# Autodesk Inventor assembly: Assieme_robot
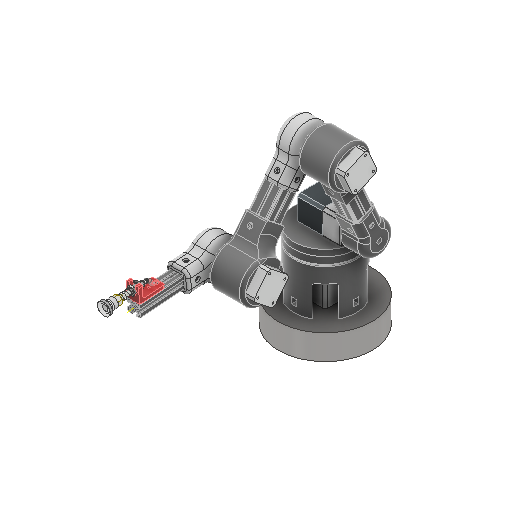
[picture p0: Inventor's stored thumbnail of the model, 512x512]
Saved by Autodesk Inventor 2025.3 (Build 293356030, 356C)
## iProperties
Created: 2026-03
Part Number: Assieme_robot
Document SubType Name: Assembly
Designer: R5800u
Author: R5800u
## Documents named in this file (17)
- C:\Users\R5800u\Desktop\robot_riduttore_cicloidale3\Workgroups\NotInProject\Assieme_robot.iam
- C:\Users\R5800u\Desktop\robot_riduttore_cicloidale3\Workgroups\NotInProject\riduttore_cicloidale_nema17-47mm.iam
- C:\Users\R5800u\Desktop\robot_riduttore_cicloidale3\Workgroups\NotInProject\braccio1.ipt
- C:\Users\R5800u\Desktop\robot_riduttore_cicloidale3\Workgroups\NotInProject\tslot-20x20-100mm.ipt
- C:\Users\R5800u\Desktop\robot_riduttore_cicloidale3\Workgroups\NotInProject\riduttore_cicloidale_nema17-40mm.iam
- C:\Users\R5800u\Desktop\robot_riduttore_cicloidale3\Workgroups\NotInProject\base_ferro.ipt
- C:\Users\R5800u\Desktop\robot_riduttore_cicloidale3\Workgroups\NotInProject\ISO 104 - 1 11 50 x 70 x 14.ipt
- C:\Users\R5800u\Desktop\robot_riduttore_cicloidale3\Workgroups\NotInProject\blocco_base.ipt
- C:\Users\R5800u\Desktop\robot_riduttore_cicloidale3\Workgroups\NotInProject\disco_base1.ipt
- C:\Users\R5800u\Desktop\robot_riduttore_cicloidale3\Workgroups\NotInProject\disco_base2.ipt
- C:\Users\R5800u\Documents\Inventor\Content Center Files\R2025\it-IT\AS 1112 (2)\AS 1112 - M5  Tipo 5.ipt
- C:\Users\R5800u\Documents\Inventor\Content Center Files\R2025\it-IT\ANSI B18.3.1M(6)\ANSI B18.3.1M - M5x0,8 x 50(1).ipt
- C:\Users\R5800u\Desktop\robot_riduttore_cicloidale3\Workgroups\NotInProject\blocco_nema.ipt
- C:\Users\R5800u\Desktop\robot_riduttore_cicloidale3\Workgroups\NotInProject\blocco_albero_nema.ipt
- C:\Users\R5800u\Desktop\robot_riduttore_cicloidale3\Workgroups\NotInProject\ventosa_20mm.iam
- C:\Users\R5800u\Documents\Inventor\Content Center Files\R2025\it-IT\AS 1420\AS 1420 - 1973 - M3 x 16.ipt
- C:\Users\R5800u\Desktop\robot_riduttore_cicloidale3\Workgroups\NotInProject\Assieme_frame_tslot.iam
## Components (28 placed, 16 different names)
1. riduttore_cicloidale_nema17-47mm:1 [sub-assembly] — Allineato:1, Coincidente:7, Angolo:1, Coincidente:20, Coincidente:21, Rotazionale:2, Allineato:13
2. braccio1:1 — Coincidente:7, Angolo:1, Coincidente:10, Coincidente:11, Coincidente:56, Coincidente:59, Rotazionale:2
3. tslot-20x20-100mm:1
4. riduttore_cicloidale_nema17-40mm:1 [sub-assembly] — Coincidente:13, Allineato:3, Angolo:2, Coincidente:16, Coincidente:18
5. base_ferro:1
6. UNI ISO 104 1 11 50 x 70 x 14:1 — Coincidente:14, Coincidente:15
7. blocco_base:1
8. disco_base1:1 — Coincidente:16, Coincidente:17, Coincidente:19, Angolo:6
9. disco_base2:1 — Coincidente:18, Coincidente:19, Angolo:3, Coincidente:20
10. Vite forgiata a testa incassata - Metrico M5x0,8 x 50:1 — Coincidente:30
11. Vite forgiata a testa incassata - Metrico M5x0,8 x 50:2 — Coincidente:32
12. Vite forgiata a testa incassata - Metrico M5x0,8 x 50:3 — Coincidente:34
13. Vite forgiata a testa incassata - Metrico M5x0,8 x 50:4 — Coincidente:36
14. blocco_nema:1
15. riduttore_cicloidale_nema17-40mm:2 [sub-assembly] — Coincidente:39, Angolo:4, Allineato:10, Coincidente:40
16. blocco_albero_nema:1 — Coincidente:40, Coincidente:41, Coincidente:42, Coincidente:43, Coincidente:44
17. tslot-20x20-100mm:2
18. blocco_nema:2
19. riduttore_cicloidale_nema17-40mm:3 [sub-assembly] — Coincidente:47, Angolo:5, Coincidente:48, Coincidente:49
20. blocco_albero_nema:2 — Coincidente:49, Coincidente:50, Coincidente:51, Coincidente:52, Coincidente:53, Coincidente:55
21. ventosa_20mm:1 [sub-assembly] — Coincidente:51, Coincidente:52, Coincidente:53
22. AS 1420 - Metrico M3 x 16:1 — Coincidente:55
23. Assieme_frame_tslot:1 [sub-assembly] — Coincidente:57, Coincidente:58, Coincidente:59, Coincidente:63
24. Assieme_frame_tslot:2 [sub-assembly] — Coincidente:60, Coincidente:61, Coincidente:62
25. AS 1112 (2) - Metrico M5  Tipo 5:1
26. AS 1112 (2) - Metrico M5  Tipo 5:2
27. AS 1112 (2) - Metrico M5  Tipo 5:3
28. AS 1112 (2) - Metrico M5  Tipo 5:4
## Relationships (49: Mate 38, Angle 6, Flush 4, RevoluteJoint 1)
- Allineato:1 [Flush]: riduttore_cicloidale_nema17-47mm:1
- Coincidente:7 [Mate]: riduttore_cicloidale_nema17-47mm:1 ↔ braccio1:1
- Angolo:1 [Angle]: riduttore_cicloidale_nema17-47mm:1 ↔ braccio1:1
- Coincidente:10 [Mate]: braccio1:1
- Coincidente:11 [Mate]: braccio1:1
- Coincidente:13 [Mate]: riduttore_cicloidale_nema17-40mm:1
- Allineato:3 [Flush]: riduttore_cicloidale_nema17-40mm:1
- Coincidente:14 [Mate]: UNI ISO 104 1 11 50 x 70 x 14:1
- Coincidente:15 [Mate]: UNI ISO 104 1 11 50 x 70 x 14:1
- Angolo:2 [Angle]: riduttore_cicloidale_nema17-40mm:1
- Coincidente:16 [Mate]: riduttore_cicloidale_nema17-40mm:1 ↔ disco_base1:1
- Coincidente:17 [Mate]: disco_base1:1
- Coincidente:18 [Mate]: riduttore_cicloidale_nema17-40mm:1 ↔ disco_base2:1
- Coincidente:19 [Mate]: disco_base1:1 ↔ disco_base2:1
- Angolo:3 [Angle]: disco_base2:1
- Coincidente:20 [Mate]: riduttore_cicloidale_nema17-47mm:1 ↔ disco_base2:1
- Coincidente:21 [Mate]: riduttore_cicloidale_nema17-47mm:1
- Coincidente:30 [Mate]: Vite forgiata a testa incassata - Metrico M5x0,8 x 50:1
- Coincidente:32 [Mate]: Vite forgiata a testa incassata - Metrico M5x0,8 x 50:2
- Coincidente:34 [Mate]: Vite forgiata a testa incassata - Metrico M5x0,8 x 50:3
- Coincidente:36 [Mate]: Vite forgiata a testa incassata - Metrico M5x0,8 x 50:4
- Coincidente:39 [Mate]: riduttore_cicloidale_nema17-40mm:2
- Angolo:4 [Angle]: riduttore_cicloidale_nema17-40mm:2
- Allineato:10 [Flush]: riduttore_cicloidale_nema17-40mm:2
- Coincidente:40 [Mate]: riduttore_cicloidale_nema17-40mm:2 ↔ blocco_albero_nema:1
- Coincidente:41 [Mate]: blocco_albero_nema:1
- Coincidente:42 [Mate]: blocco_albero_nema:1
- Coincidente:43 [Mate]: blocco_albero_nema:1
- Coincidente:44 [Mate]: blocco_albero_nema:1
- Coincidente:47 [Mate]: riduttore_cicloidale_nema17-40mm:3
- Angolo:5 [Angle]: riduttore_cicloidale_nema17-40mm:3
- Coincidente:48 [Mate]: riduttore_cicloidale_nema17-40mm:3
- Coincidente:49 [Mate]: riduttore_cicloidale_nema17-40mm:3 ↔ blocco_albero_nema:2
- Coincidente:50 [Mate]: blocco_albero_nema:2
- Coincidente:51 [Mate]: blocco_albero_nema:2 ↔ ventosa_20mm:1
- Coincidente:52 [Mate]: blocco_albero_nema:2 ↔ ventosa_20mm:1
- Coincidente:53 [Mate]: blocco_albero_nema:2 ↔ ventosa_20mm:1
- Coincidente:55 [Mate]: blocco_albero_nema:2 ↔ AS 1420 - Metrico M3 x 16:1
- Angolo:6 [Angle]: disco_base1:1
- Coincidente:56 [Mate]: braccio1:1
- Coincidente:57 [Mate]: Assieme_frame_tslot:1
- Coincidente:58 [Mate]: Assieme_frame_tslot:1
- Coincidente:59 [Mate]: braccio1:1 ↔ Assieme_frame_tslot:1
- Coincidente:60 [Mate]: Assieme_frame_tslot:2
- Coincidente:61 [Mate]: Assieme_frame_tslot:2
- Coincidente:62 [Mate]: Assieme_frame_tslot:2
- Rotazionale:2 [RevoluteJoint]: riduttore_cicloidale_nema17-47mm:1 ↔ braccio1:1
- Coincidente:63 [Mate]: Assieme_frame_tslot:1
- Allineato:13 [Flush]: riduttore_cicloidale_nema17-47mm:1
